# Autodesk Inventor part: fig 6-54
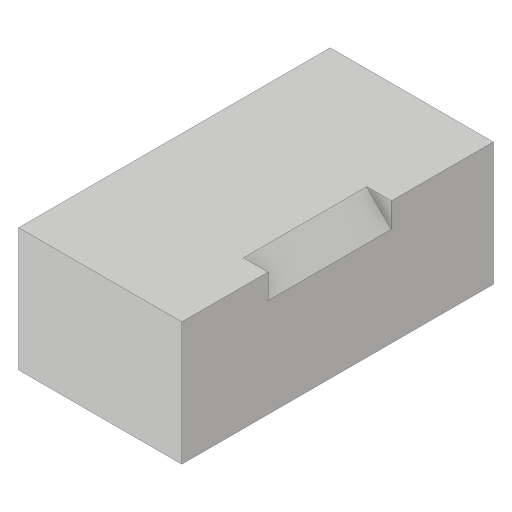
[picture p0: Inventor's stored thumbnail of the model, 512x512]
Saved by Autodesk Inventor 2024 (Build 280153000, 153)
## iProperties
Created: 2018-03
Part Number: fig 6-54
Material: Generic
Document SubType Name: Modeling
Designer: CADCIM 00
Density: 1 g/cm^3
Appearance: Default
Author: CADCIM 00
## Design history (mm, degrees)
sketch "Sketch1"
  geometry: L1 (0, 0)-(13.237, 0); L2 (13.237, 0)-(13.237, -25.282); L3 (13.237, -25.282)-(0, -25.282); L4 (0, -25.282)-(0, 0)
  constraints: 8 end point, 2 parallel, 1 horizontal, 1 perpendicular
extrude "Extrusion1" new body sketch "Sketch1" distance "d0" = 10; taper "d1" = 0 deg
chamfer "Chamfer1" distance "d2" = 2; stored, may be unused: second distance "d3" = 2, angle "d4" = 45 deg; dims "d5" = 7, "d6" = 10, "d7" = 8.28246
body "Solid1"
